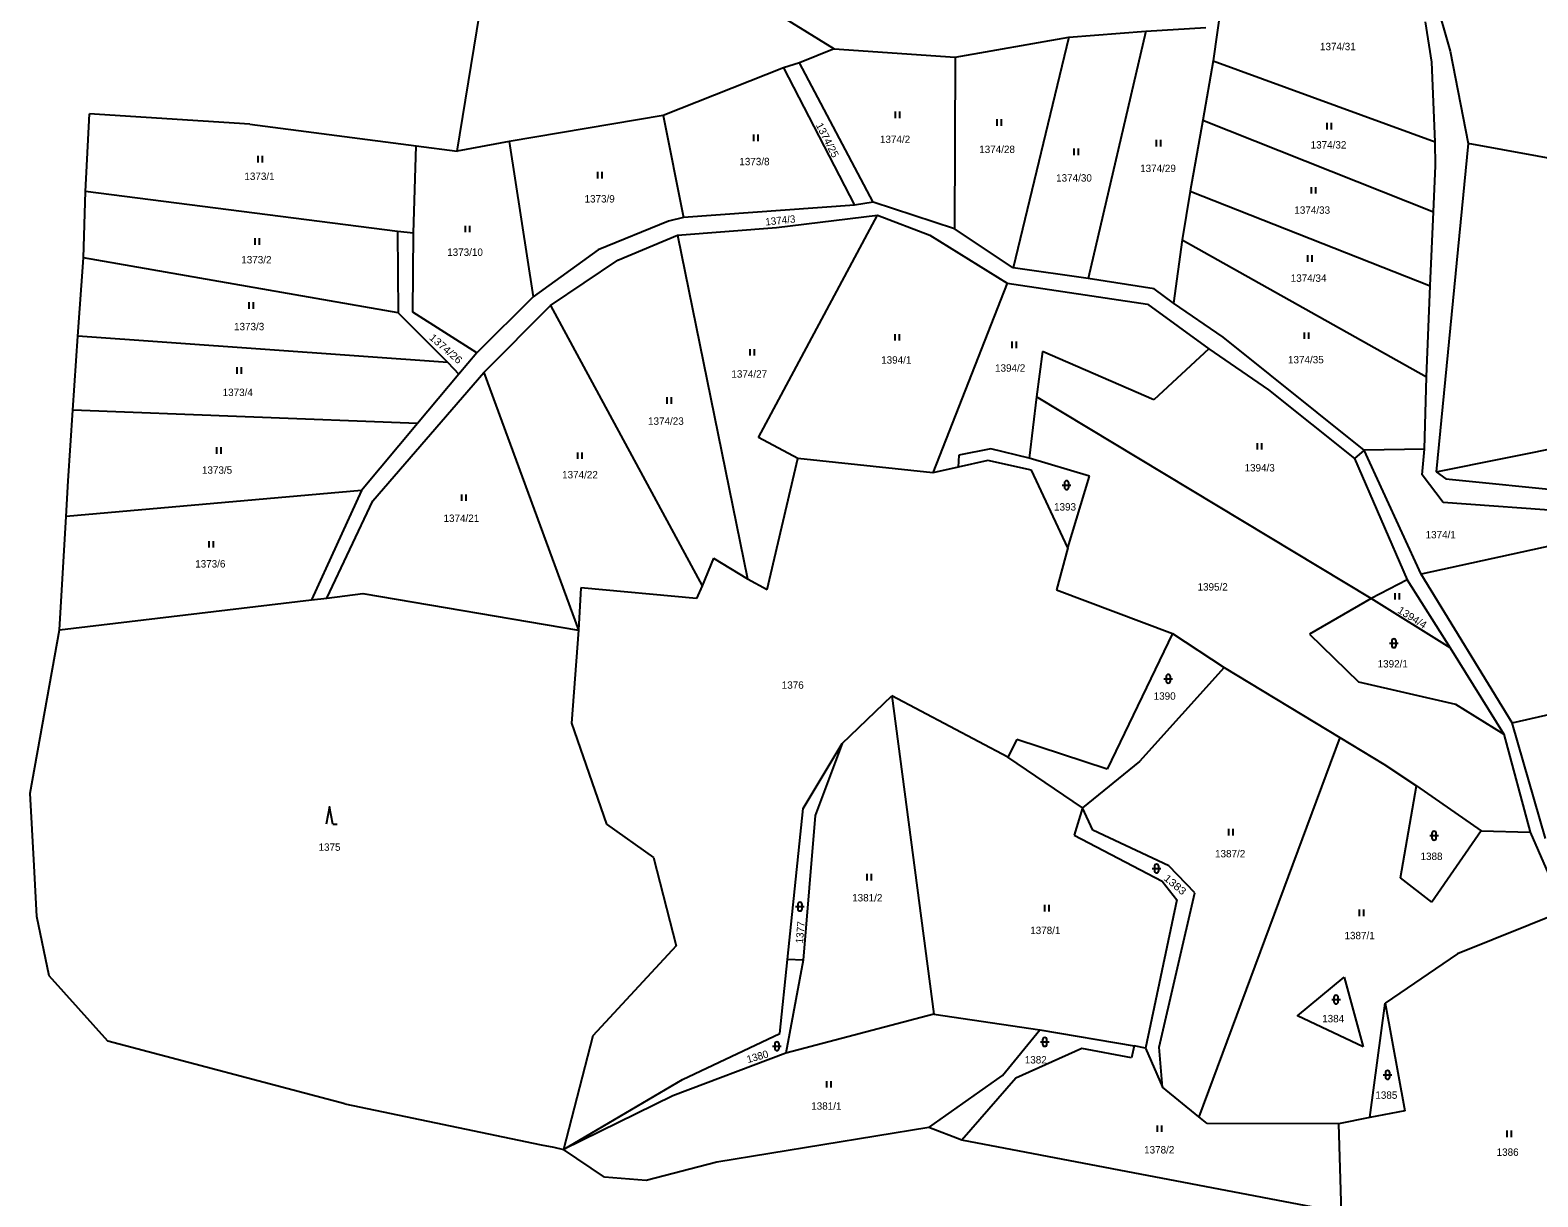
# Model space of a CAD drawing. Extents: x -820420 to -815896, y -1105820 to -1103643.
# Drawn here: x -820420.4 to -820073.7, y -1104812.4 to -1104544.2 of the extents above; entities that cross this region are included whole.
import ezdxf
from ezdxf.enums import TextEntityAlignment as Align

# ---------------------------------------------------------------- set-up
doc = ezdxf.new("R2010")
doc.units = 0
doc.header["$LTSCALE"] = 0.68
doc.layers.add('1', color=7, linetype='Continuous', lineweight=25)
doc.layers.add('3', color=7, linetype='Continuous', lineweight=25)
doc.layers.add('2', color=7, linetype='Continuous')

msp = doc.modelspace()

# ---------------------------------------------------------------- linework, layer by layer
at = {"layer": '1'}
for p, q in [((-820322.27, -1104572.03), (-820311.34, -1104505.14)), ((-820101.65, -1104521.52), (-820093.92, -1104549.11)), ((-820255.58, -1104536.13), (-820235.58, -1104548.52)), ((-820146.57, -1104538.3), (-820148.41, -1104551.26)), ((-820098.08, -1104551.57), (-820099.57, -1104542.35)), ((-820207.68, -1104550.44), (-820181.59, -1104545.87)), ((-820181.59, -1104545.87), (-820194.41, -1104598.85)), ((-820181.59, -1104545.87), (-820163.87, -1104544.47)), ((-820163.87, -1104544.47), (-820177.12, -1104601.31)), ((-820163.87, -1104544.47), (-820150.09, -1104543.67)), ((-820235.58, -1104548.52), (-820243.53, -1104551.74)), ((-820235.58, -1104548.52), (-820207.68, -1104550.44)), ((-820093.92, -1104549.11), (-820089.78, -1104570.31)), ((-820243.53, -1104551.74), (-820247.22, -1104552.89)), ((-820226.58, -1104583.77), (-820243.53, -1104551.74)), ((-820207.68, -1104550.44), (-820207.85, -1104589.89)), ((-820148.41, -1104551.26), (-820150.8, -1104564.9)), ((-820148.41, -1104551.26), (-820097.32, -1104569.89)), ((-820097.32, -1104569.89), (-820098.08, -1104551.57)), ((-820247.22, -1104552.89), (-820274.83, -1104563.88)), ((-820247.22, -1104552.89), (-820230.86, -1104584.47)), ((-820407.73, -1104581.36), (-820406.78, -1104563.5)), ((-820404.47, -1104563.65), (-820406.78, -1104563.5)), ((-820369.9, -1104565.87), (-820404.47, -1104563.65)), ((-820369.9, -1104565.87), (-820331.64, -1104570.82)), ((-820274.83, -1104563.88), (-820310.31, -1104569.86)), ((-820274.83, -1104563.88), (-820270.16, -1104587.34)), ((-820150.8, -1104564.9), (-820153.66, -1104581.29)), ((-820150.8, -1104564.9), (-820097.74, -1104585.97)), ((-820310.31, -1104569.86), (-820322.27, -1104572.03)), ((-820310.31, -1104569.86), (-820304.8, -1104605.58)), ((-820097.29, -1104575.43), (-820097.32, -1104569.89)), ((-820332.26, -1104590.89), (-820331.64, -1104570.82)), ((-820331.64, -1104570.82), (-820322.27, -1104572.03)), ((-820089.78, -1104570.31), (-820097.13, -1104645.78)), ((-820031.99, -1104580.82), (-820089.78, -1104570.31)), ((-820097.74, -1104585.97), (-820097.29, -1104575.43)), ((-820408.17, -1104596.57), (-820407.73, -1104581.36)), ((-820335.94, -1104590.54), (-820407.73, -1104581.36)), ((-820226.58, -1104583.77), (-820230.86, -1104584.47)), ((-820207.85, -1104589.89), (-820226.58, -1104583.77)), ((-820153.66, -1104581.29), (-820155.5, -1104592.47)), ((-820153.66, -1104581.29), (-820098.46, -1104603.05)), ((-820270.16, -1104587.34), (-820273.62, -1104588.15)), ((-820230.86, -1104584.47), (-820270.16, -1104587.34)), ((-820252.93, -1104637.9), (-820225.56, -1104586.8)), ((-820248.82, -1104589.59), (-820225.56, -1104586.8)), ((-820225.56, -1104586.8), (-820213.53, -1104591.39)), ((-820098.46, -1104603.05), (-820097.74, -1104585.97)), ((-820335.94, -1104590.54), (-820335.81, -1104609.19)), ((-820332.26, -1104590.89), (-820335.94, -1104590.54)), ((-820332.47, -1104609.08), (-820332.26, -1104590.89)), ((-820273.62, -1104588.15), (-820289.84, -1104594.76)), ((-820271.57, -1104591.39), (-820248.82, -1104589.59)), ((-820194.41, -1104598.85), (-820207.85, -1104589.89)), ((-820285.27, -1104597.13), (-820271.57, -1104591.39)), ((-820271.57, -1104591.39), (-820255.5, -1104670.36)), ((-820213.53, -1104591.39), (-820195.75, -1104602.38)), ((-820155.5, -1104592.47), (-820157.48, -1104606.99)), ((-820155.5, -1104592.47), (-820099.35, -1104623.9)), ((-820409.51, -1104614.56), (-820408.17, -1104596.57)), ((-820335.81, -1104609.19), (-820408.17, -1104596.57)), ((-820289.84, -1104594.76), (-820304.8, -1104605.58)), ((-820300.79, -1104607.57), (-820285.27, -1104597.13)), ((-820177.12, -1104601.31), (-820194.41, -1104598.85)), ((-820161.95, -1104603.74), (-820177.12, -1104601.31)), ((-820195.75, -1104602.38), (-820212.89, -1104645.98)), ((-820195.75, -1104602.38), (-820163.5, -1104607.22)), ((-820157.48, -1104606.99), (-820161.95, -1104603.74)), ((-820099.35, -1104623.9), (-820098.46, -1104603.05)), ((-820304.8, -1104605.58), (-820317.74, -1104618.42)), ((-820300.79, -1104607.57), (-820265.87, -1104672)), ((-820163.5, -1104607.22), (-820149.35, -1104617.51)), ((-820146.07, -1104614.83), (-820157.48, -1104606.99)), ((-820335.81, -1104609.19), (-820324.41, -1104620.68)), ((-820317.74, -1104618.42), (-820332.47, -1104609.08)), ((-820410.65, -1104631.6), (-820409.51, -1104614.56)), ((-820324.41, -1104620.68), (-820409.51, -1104614.56)), ((-820113.67, -1104640.82), (-820146.07, -1104614.83)), ((-820317.74, -1104618.42), (-820321.87, -1104623.31)), ((-820187.64, -1104618.09), (-820188.98, -1104628.51)), ((-820162.05, -1104629.2), (-820187.64, -1104618.09)), ((-820149.35, -1104617.51), (-820162.05, -1104629.2)), ((-820149.35, -1104617.51), (-820135.64, -1104626.94)), ((-820324.41, -1104620.68), (-820321.87, -1104623.31)), ((-820321.87, -1104623.31), (-820331.38, -1104634.68)), ((-820316.1, -1104622.92), (-820294.37, -1104682.17)), ((-820099.78, -1104640.6), (-820099.35, -1104623.9)), ((-820188.98, -1104628.51), (-820190.68, -1104642.6)), ((-820112.07, -1104674.91), (-820188.98, -1104628.51)), ((-820135.64, -1104626.94), (-820115.92, -1104642.7)), ((-820411.67, -1104647.86), (-820410.65, -1104631.6)), ((-820331.38, -1104634.68), (-820410.65, -1104631.6)), ((-820331.38, -1104634.68), (-820344.25, -1104650.05)), ((-820097.13, -1104645.78), (-820040.81, -1104634.47)), ((-820243.93, -1104642.72), (-820252.93, -1104637.9)), ((-820250.94, -1104672.84), (-820243.93, -1104642.72)), ((-820212.89, -1104645.98), (-820243.93, -1104642.72)), ((-820206.84, -1104641.95), (-820207.06, -1104644.71)), ((-820199.55, -1104640.51), (-820206.84, -1104641.95)), ((-820190.68, -1104642.6), (-820199.55, -1104640.51)), ((-820176.85, -1104646.77), (-820190.68, -1104642.6)), ((-820113.67, -1104640.82), (-820115.92, -1104642.7)), ((-820115.92, -1104642.7), (-820103.77, -1104670.61)), ((-820099.78, -1104640.6), (-820113.67, -1104640.82)), ((-820100.57, -1104669.28), (-820113.67, -1104640.82)), ((-820100.31, -1104646.47), (-820099.78, -1104640.6)), ((-820207.06, -1104644.71), (-820212.89, -1104645.98)), ((-820200.18, -1104643.16), (-820207.06, -1104644.71)), ((-820190.17, -1104645.42), (-820200.18, -1104643.16)), ((-820181.78, -1104663.22), (-820190.17, -1104645.42)), ((-820097.13, -1104645.78), (-820094.87, -1104647.41)), ((-820412.18, -1104656.02), (-820411.67, -1104647.86)), ((-820181.78, -1104663.22), (-820176.85, -1104646.77)), ((-820095.52, -1104652.81), (-820100.31, -1104646.47)), ((-820094.87, -1104647.41), (-819998.85, -1104656.93)), ((-820344.25, -1104650.05), (-820412.18, -1104656.02)), ((-820344.25, -1104650.05), (-820355.74, -1104675.19)), ((-820352.22, -1104674.8), (-820341.67, -1104652.41)), ((-820006.15, -1104659.33), (-820095.52, -1104652.81)), ((-820413.7, -1104682.12), (-820412.18, -1104656.02)), ((-820050.48, -1104658.34), (-820100.57, -1104669.28)), ((-820181.78, -1104663.22), (-820184.43, -1104672.94)), ((-820263.32, -1104665.6), (-820265.87, -1104672)), ((-820263.32, -1104665.6), (-820255.5, -1104670.36)), ((-820255.5, -1104670.36), (-820250.94, -1104672.84)), ((-820103.77, -1104670.61), (-820112.07, -1104674.91)), ((-820103.77, -1104670.61), (-820093.88, -1104686.21)), ((-820079.62, -1104703.51), (-820100.57, -1104669.28)), ((-820343.94, -1104673.76), (-820294.37, -1104682.17)), ((-820293.84, -1104672.43), (-820294.37, -1104682.17)), ((-820267.23, -1104674.91), (-820293.84, -1104672.43)), ((-820265.87, -1104672), (-820267.23, -1104674.91)), ((-820184.43, -1104672.94), (-820157.74, -1104682.93)), ((-820413.7, -1104682.12), (-820355.74, -1104675.19)), ((-820112.07, -1104674.91), (-820126.27, -1104683.09)), ((-820093.88, -1104686.21), (-820112.07, -1104674.91)), ((-820420.44, -1104719.68), (-820413.7, -1104682.12)), ((-820294.37, -1104682.17), (-820295.92, -1104703.52)), ((-820157.74, -1104682.93), (-820172.77, -1104714.11)), ((-820157.74, -1104682.93), (-820145.82, -1104690.77)), ((-820126.27, -1104683.09), (-820114.98, -1104694.03)), ((-820093.88, -1104686.21), (-820081.55, -1104706.09)), ((-820145.82, -1104690.77), (-820165.36, -1104712.39)), ((-820145.82, -1104690.77), (-820119.26, -1104706.82)), ((-820079.62, -1104703.51), (-820020.46, -1104689.78)), ((-820114.98, -1104694.03), (-820092.66, -1104699.19)), ((-820233.68, -1104708.2), (-820222.31, -1104697.24)), ((-820222.31, -1104697.24), (-820212.65, -1104770.42)), ((-820195.6, -1104711.37), (-820222.31, -1104697.24)), ((-820092.66, -1104699.19), (-820081.55, -1104706.09)), ((-820295.92, -1104703.52), (-820287.88, -1104726.8)), ((-820071.97, -1104730.07), (-820079.62, -1104703.51)), ((-820242.65, -1104723.19), (-820233.68, -1104708.2)), ((-820233.68, -1104708.2), (-820239.94, -1104724.81)), ((-820193.51, -1104707.33), (-820195.6, -1104711.37)), ((-820172.77, -1104714.11), (-820193.51, -1104707.33)), ((-820119.26, -1104706.82), (-820151.69, -1104794.05)), ((-820119.26, -1104706.82), (-820109.15, -1104712.94)), ((-820081.55, -1104706.09), (-820075.47, -1104728.61)), ((-820178.43, -1104723.05), (-820195.6, -1104711.37)), ((-820165.36, -1104712.39), (-820178.43, -1104723.05)), ((-820109.15, -1104712.94), (-820101.65, -1104717.98)), ((-820105.3, -1104739.12), (-820101.65, -1104717.98)), ((-820101.65, -1104717.98), (-820086.79, -1104728.33)), ((-820419.49, -1104736.33), (-820420.44, -1104719.68)), ((-820246.28, -1104757.85), (-820242.65, -1104723.19)), ((-820239.94, -1104724.81), (-820242.65, -1104758.07)), ((-820178.43, -1104723.05), (-820180.38, -1104729.28)), ((-820176.09, -1104728.13), (-820178.43, -1104723.05)), ((-820287.88, -1104726.8), (-820277.11, -1104734.43)), ((-820180.38, -1104729.28), (-820160.1, -1104739.84)), ((-820158.56, -1104736.37), (-820176.09, -1104728.13)), ((-820086.79, -1104728.33), (-820098.09, -1104744.67)), ((-820086.79, -1104728.33), (-820075.47, -1104728.61)), ((-820075.47, -1104728.61), (-820067.61, -1104746.67)), ((-820418.91, -1104748.03), (-820419.49, -1104736.33)), ((-820277.11, -1104734.43), (-820271.89, -1104754.75)), ((-820152.62, -1104742.52), (-820158.56, -1104736.37)), ((-820160.1, -1104739.84), (-820156.75, -1104744.13)), ((-820098.09, -1104744.67), (-820105.3, -1104739.12)), ((-820160.77, -1104778.04), (-820152.62, -1104742.52)), ((-820156.75, -1104744.13), (-820163.96, -1104778.25)), ((-820067.61, -1104746.67), (-820092.16, -1104756.59)), ((-820416.06, -1104761.67), (-820418.91, -1104748.03)), ((-820271.89, -1104754.75), (-820291.01, -1104775.44)), ((-820092.16, -1104756.59), (-820108.81, -1104767.95)), ((-820248.05, -1104774.89), (-820246.28, -1104757.85)), ((-820242.65, -1104758.07), (-820246.69, -1104779.42)), ((-820242.65, -1104758.07), (-820246.28, -1104757.85)), ((-820402.54, -1104776.65), (-820416.06, -1104761.67)), ((-820118.23, -1104761.96), (-820113.9, -1104777.94)), ((-820212.65, -1104770.42), (-820246.69, -1104779.42)), ((-820212.65, -1104770.42), (-820188.24, -1104774.07)), ((-820112.36, -1104794.22), (-820108.81, -1104767.95)), ((-820108.81, -1104767.95), (-820104.28, -1104792.67)), ((-820196.87, -1104784.51), (-820188.24, -1104774.07)), ((-820188.24, -1104774.07), (-820166.58, -1104777.7)), ((-820348.11, -1104791.07), (-820402.54, -1104776.65)), ((-820291.01, -1104775.44), (-820297.76, -1104801.53)), ((-820270.45, -1104785.46), (-820248.05, -1104774.89)), ((-820166.58, -1104777.7), (-820167.2, -1104780.52)), ((-820163.96, -1104778.25), (-820166.58, -1104777.7)), ((-820160.04, -1104787.24), (-820160.77, -1104778.04)), ((-820246.69, -1104779.42), (-820272.64, -1104789.22)), ((-820178.61, -1104778.37), (-820193.74, -1104785.16)), ((-820167.2, -1104780.52), (-820178.61, -1104778.37)), ((-820163.96, -1104778.25), (-820160.04, -1104787.24)), ((-820213.77, -1104796.52), (-820196.87, -1104784.51)), ((-820297.76, -1104801.53), (-820270.45, -1104785.46)), ((-820193.74, -1104785.16), (-820206.21, -1104799.44)), ((-820151.69, -1104794.05), (-820160.04, -1104787.24)), ((-820348.11, -1104791.07), (-820302.96, -1104800.45)), ((-820272.64, -1104789.22), (-820297.76, -1104801.53)), ((-820149.79, -1104795.6), (-820151.69, -1104794.05)), ((-820112.36, -1104794.22), (-820119.58, -1104795.67)), ((-820104.28, -1104792.67), (-820112.36, -1104794.22)), ((-820213.77, -1104796.52), (-820262.53, -1104804.46)), ((-820206.21, -1104799.44), (-820213.77, -1104796.52)), ((-820119.58, -1104795.67), (-820149.79, -1104795.6)), ((-820119.58, -1104795.67), (-820118.98, -1104816.05)), ((-820302.96, -1104800.45), (-820300.02, -1104801.06)), ((-820300.02, -1104801.06), (-820297.76, -1104801.53)), ((-820288.36, -1104807.89), (-820297.76, -1104801.53)), ((-820118.98, -1104816.05), (-820206.21, -1104799.44)), ((-820262.53, -1104804.46), (-820278.74, -1104808.65)), ((-820278.74, -1104808.65), (-820288.36, -1104807.89))]:
    msp.add_line(p, q, dxfattribs=at)
for points in [[(-820341.67, -1104652.41), (-820316.1, -1104622.92), (-820300.79, -1104607.57)], [(-820355.74, -1104675.19), (-820352.22, -1104674.8), (-820343.94, -1104673.76)], [(-820113.9, -1104777.94), (-820129.02, -1104770.82), (-820118.23, -1104761.96)]]:
    msp.add_lwpolyline(points, dxfattribs=at)
at = {"layer": '3'}
for p, q in [((-820221.431, -1104564.47), (-820221.431, -1104562.97)), ((-820220.43, -1104564.47), (-820220.43, -1104562.97)), ((-820198.041, -1104566.23), (-820198.041, -1104564.73)), ((-820197.04, -1104566.23), (-820197.04, -1104564.73)), ((-820122.161, -1104567.07), (-820122.161, -1104565.57)), ((-820121.16, -1104567.07), (-820121.16, -1104565.57)), ((-820254.041, -1104569.75), (-820254.041, -1104568.25)), ((-820253.04, -1104569.75), (-820253.04, -1104568.25)), ((-820161.401, -1104570.97), (-820161.401, -1104569.47)), ((-820160.4, -1104570.97), (-820160.4, -1104569.47)), ((-820368.031, -1104574.64), (-820368.031, -1104573.14)), ((-820367.03, -1104574.64), (-820367.03, -1104573.14)), ((-820180.361, -1104572.97), (-820180.361, -1104571.47)), ((-820179.36, -1104572.97), (-820179.36, -1104571.47)), ((-820289.871, -1104578.32), (-820289.871, -1104576.82)), ((-820288.87, -1104578.32), (-820288.87, -1104576.82)), ((-820125.801, -1104581.82), (-820125.801, -1104580.32)), ((-820124.8, -1104581.82), (-820124.8, -1104580.32)), ((-820320.351, -1104590.71), (-820320.351, -1104589.21)), ((-820319.35, -1104590.71), (-820319.35, -1104589.21)), ((-820368.661, -1104593.56), (-820368.661, -1104592.06)), ((-820367.66, -1104593.56), (-820367.66, -1104592.06)), ((-820126.641, -1104597.48), (-820126.641, -1104595.98)), ((-820125.64, -1104597.48), (-820125.64, -1104595.98)), ((-820370.111, -1104608.28), (-820370.111, -1104606.78)), ((-820369.11, -1104608.28), (-820369.11, -1104606.78)), ((-820221.541, -1104615.6), (-820221.541, -1104614.1)), ((-820220.54, -1104615.6), (-820220.54, -1104614.1)), ((-820127.371, -1104615.21), (-820127.371, -1104613.71)), ((-820126.37, -1104615.21), (-820126.37, -1104613.71)), ((-820254.871, -1104619.05), (-820254.871, -1104617.55)), ((-820253.87, -1104619.05), (-820253.87, -1104617.55)), ((-820194.631, -1104617.33), (-820194.631, -1104615.83)), ((-820193.63, -1104617.33), (-820193.63, -1104615.83)), ((-820372.841, -1104623.24), (-820372.841, -1104621.74)), ((-820371.84, -1104623.24), (-820371.84, -1104621.74)), ((-820273.921, -1104630.13), (-820273.921, -1104628.63)), ((-820272.92, -1104630.13), (-820272.92, -1104628.63)), ((-820138.201, -1104640.68), (-820138.201, -1104639.18)), ((-820137.2, -1104640.68), (-820137.2, -1104639.18)), ((-820377.491, -1104641.62), (-820377.491, -1104640.12)), ((-820376.49, -1104641.62), (-820376.49, -1104640.12)), ((-820294.511, -1104642.81), (-820294.511, -1104641.31)), ((-820293.51, -1104642.81), (-820293.51, -1104641.31)), ((-820183.101, -1104648.841), (-820181.099, -1104648.841)), ((-820182.601, -1104648.341), (-820182.601, -1104649.342)), ((-820181.599, -1104649.342), (-820181.599, -1104648.341)), ((-820321.181, -1104652.46), (-820321.181, -1104650.96)), ((-820320.18, -1104652.46), (-820320.18, -1104650.96)), ((-820379.281, -1104663.18), (-820379.281, -1104661.68)), ((-820378.28, -1104663.18), (-820378.28, -1104661.68)), ((-820106.561, -1104675.13), (-820106.561, -1104673.63)), ((-820105.56, -1104675.13), (-820105.56, -1104673.63)), ((-820107.831, -1104685.191), (-820105.829, -1104685.191)), ((-820107.331, -1104684.691), (-820107.331, -1104685.692)), ((-820106.329, -1104685.692), (-820106.329, -1104684.691)), ((-820159.721, -1104693.351), (-820157.719, -1104693.351)), ((-820159.221, -1104692.851), (-820159.221, -1104693.852)), ((-820158.219, -1104693.852), (-820158.219, -1104692.851)), ((-820350.86, -1104726.79), (-820349.864, -1104726.79)), ((-820144.751, -1104729.34), (-820144.751, -1104727.84)), ((-820143.75, -1104729.34), (-820143.75, -1104727.84)), ((-820098.571, -1104729.411), (-820096.569, -1104729.411)), ((-820098.071, -1104728.911), (-820098.071, -1104729.912)), ((-820097.069, -1104729.912), (-820097.069, -1104728.911)), ((-820161.911, -1104736.481), (-820161.911, -1104737.482)), ((-820160.909, -1104737.482), (-820160.909, -1104736.481)), ((-820227.961, -1104739.7), (-820227.961, -1104738.2)), ((-820226.96, -1104739.7), (-820226.96, -1104738.2)), ((-820162.411, -1104736.981), (-820160.409, -1104736.981)), ((-820244.411, -1104745.731), (-820242.409, -1104745.731)), ((-820243.911, -1104745.231), (-820243.911, -1104746.232)), ((-820242.909, -1104746.232), (-820242.909, -1104745.231)), ((-820187.131, -1104746.85), (-820187.131, -1104745.35)), ((-820186.13, -1104746.85), (-820186.13, -1104745.35)), ((-820114.751, -1104747.92), (-820114.751, -1104746.42)), ((-820113.75, -1104747.92), (-820113.75, -1104746.42)), ((-820121.131, -1104767.081), (-820119.129, -1104767.081)), ((-820120.631, -1104766.581), (-820120.631, -1104767.582)), ((-820119.629, -1104767.582), (-820119.629, -1104766.581)), ((-820249.721, -1104777.811), (-820247.719, -1104777.811)), ((-820249.221, -1104777.311), (-820249.221, -1104778.312)), ((-820248.219, -1104778.312), (-820248.219, -1104777.311)), ((-820188.101, -1104776.841), (-820186.099, -1104776.841)), ((-820187.601, -1104776.341), (-820187.601, -1104777.342)), ((-820186.599, -1104777.342), (-820186.599, -1104776.341)), ((-820109.291, -1104784.411), (-820107.289, -1104784.411)), ((-820108.791, -1104783.911), (-820108.791, -1104784.912)), ((-820107.789, -1104784.912), (-820107.789, -1104783.911)), ((-820237.251, -1104787.34), (-820237.251, -1104785.84)), ((-820236.25, -1104787.34), (-820236.25, -1104785.84)), ((-820161.181, -1104797.52), (-820161.181, -1104796.02)), ((-820160.18, -1104797.52), (-820160.18, -1104796.02)), ((-820080.781, -1104798.69), (-820080.781, -1104797.19)), ((-820079.78, -1104798.69), (-820079.78, -1104797.19))]:
    msp.add_line(p, q, dxfattribs=at)
msp.add_lwpolyline([(-820350.86, -1104726.79), (-820351.61, -1104722.79), (-820352.36, -1104726.79)], dxfattribs=at)
for centre, start, end in [((-820182.1, -1104648.3409), 0, 180), ((-820182.1, -1104649.3409), 180, 359.98789), ((-820106.83, -1104684.6909), 0, 180), ((-820106.83, -1104685.6909), 180, 359.98789), ((-820158.72, -1104692.8509), 0, 180), ((-820158.72, -1104693.8509), 180, 359.98789), ((-820097.57, -1104728.9109), 0, 180), ((-820097.57, -1104729.9109), 180, 359.98789), ((-820161.41, -1104736.4809), 0, 180), ((-820161.41, -1104737.4809), 180, 359.98789), ((-820243.41, -1104745.2309), 0, 180), ((-820243.41, -1104746.2309), 180, 359.98789), ((-820120.13, -1104766.5809), 0, 180), ((-820120.13, -1104767.5809), 180, 359.98789), ((-820248.72, -1104777.3109), 0, 180), ((-820187.1, -1104776.3409), 0, 180), ((-820187.1, -1104777.3409), 180, 359.98789), ((-820248.72, -1104778.3109), 180, 359.98789), ((-820108.29, -1104783.9109), 0, 180), ((-820108.29, -1104784.9109), 180, 359.98789)]:
    msp.add_arc(centre, 0.5, start, end, dxfattribs=at)

# ---------------------------------------------------------------- texts
at = {"layer": '2'}
for s, p in [('1374/31', (-820119.709, -1104548.855)), ('1374/2', (-820221.54, -1104570.185)), ('1374/32', (-820121.859, -1104571.455)), ('1373/8', (-820253.88, -1104575.295)), ('1374/28', (-820198.079, -1104572.485)), ('1373/1', (-820367.7, -1104578.685)), ('1374/29', (-820161.069, -1104576.865)), ('1374/30', (-820180.389, -1104579.055)), ('1373/9', (-820289.48, -1104583.865)), ('1374/33', (-820125.609, -1104586.455)), ('1373/10', (-820320.429, -1104596.135)), ('1373/2', (-820368.41, -1104597.865)), ('1374/34', (-820126.439, -1104602.095)), ('1373/3', (-820370.08, -1104613.225)), ('1394/1', (-820221.26, -1104620.905)), ('1394/2', (-820195.07, -1104622.755)), ('1374/35', (-820127.069, -1104620.845)), ('1374/27', (-820255.069, -1104624.125)), ('1373/4', (-820372.7, -1104628.355)), ('1374/23', (-820274.239, -1104634.965)), ('1373/5', (-820377.46, -1104646.215)), ('1374/22', (-820293.999, -1104647.285)), ('1394/3', (-820137.69, -1104645.695)), ('1393', (-820182.45, -1104654.675)), ('1374/21', (-820321.269, -1104657.295)), ('1374/1', (-820096.06, -1104661.075)), ('1373/6', (-820379.01, -1104667.775)), ('1395/2', (-820148.5, -1104673.075)), ('1392/1', (-820107.09, -1104690.755)), ('1376', (-820245.07, -1104695.645)), ('1390', (-820159.54, -1104698.165)), ('1375', (-820351.6, -1104732.895)), ('1387/2', (-820144.48, -1104734.405)), ('1388', (-820098.17, -1104735.005)), ('1381/2', (-820227.93, -1104744.535)), ('1378/1', (-820186.98, -1104752.035)), ('1387/1', (-820114.71, -1104753.225)), ('1384', (-820120.79, -1104772.315)), ('1382', (-820189.18, -1104781.785)), ('1385', (-820108.56, -1104789.905)), ('1381/1', (-820237.34, -1104792.415)), ('1378/2', (-820160.79, -1104802.475)), ('1386', (-820080.67, -1104803.015))]:
    msp.add_text(s, height=1.7, dxfattribs=at).set_placement(p, align=Align.CENTER)
for s, rotation, width, p in [('1374/25', 297, 1.05, (-820237.8481, -1104569.8986)), ('1374/26', 319, 1.1, (-820325.4041, -1104618.1176)), ('1394/4', 328, 1.05, (-820103.0449, -1104679.9733)), ('1383', 320, 1.15, (-820157.6844, -1104741.3281))]:
    msp.add_text(s, height=1.7, rotation=rotation, dxfattribs=dict(at, width=width)).set_placement(p, align=Align.CENTER)
for s, rotation, p in [('1374/3', 6, (-820247.8393, -1104588.8079)), ('1377', 85, (-820242.503, -1104751.7286)), ('1380', 16, (-820252.9428, -1104781.0137))]:
    msp.add_text(s, height=1.7, rotation=rotation, dxfattribs=at).set_placement(p, align=Align.CENTER)

doc.saveas('drawing.dxf')
